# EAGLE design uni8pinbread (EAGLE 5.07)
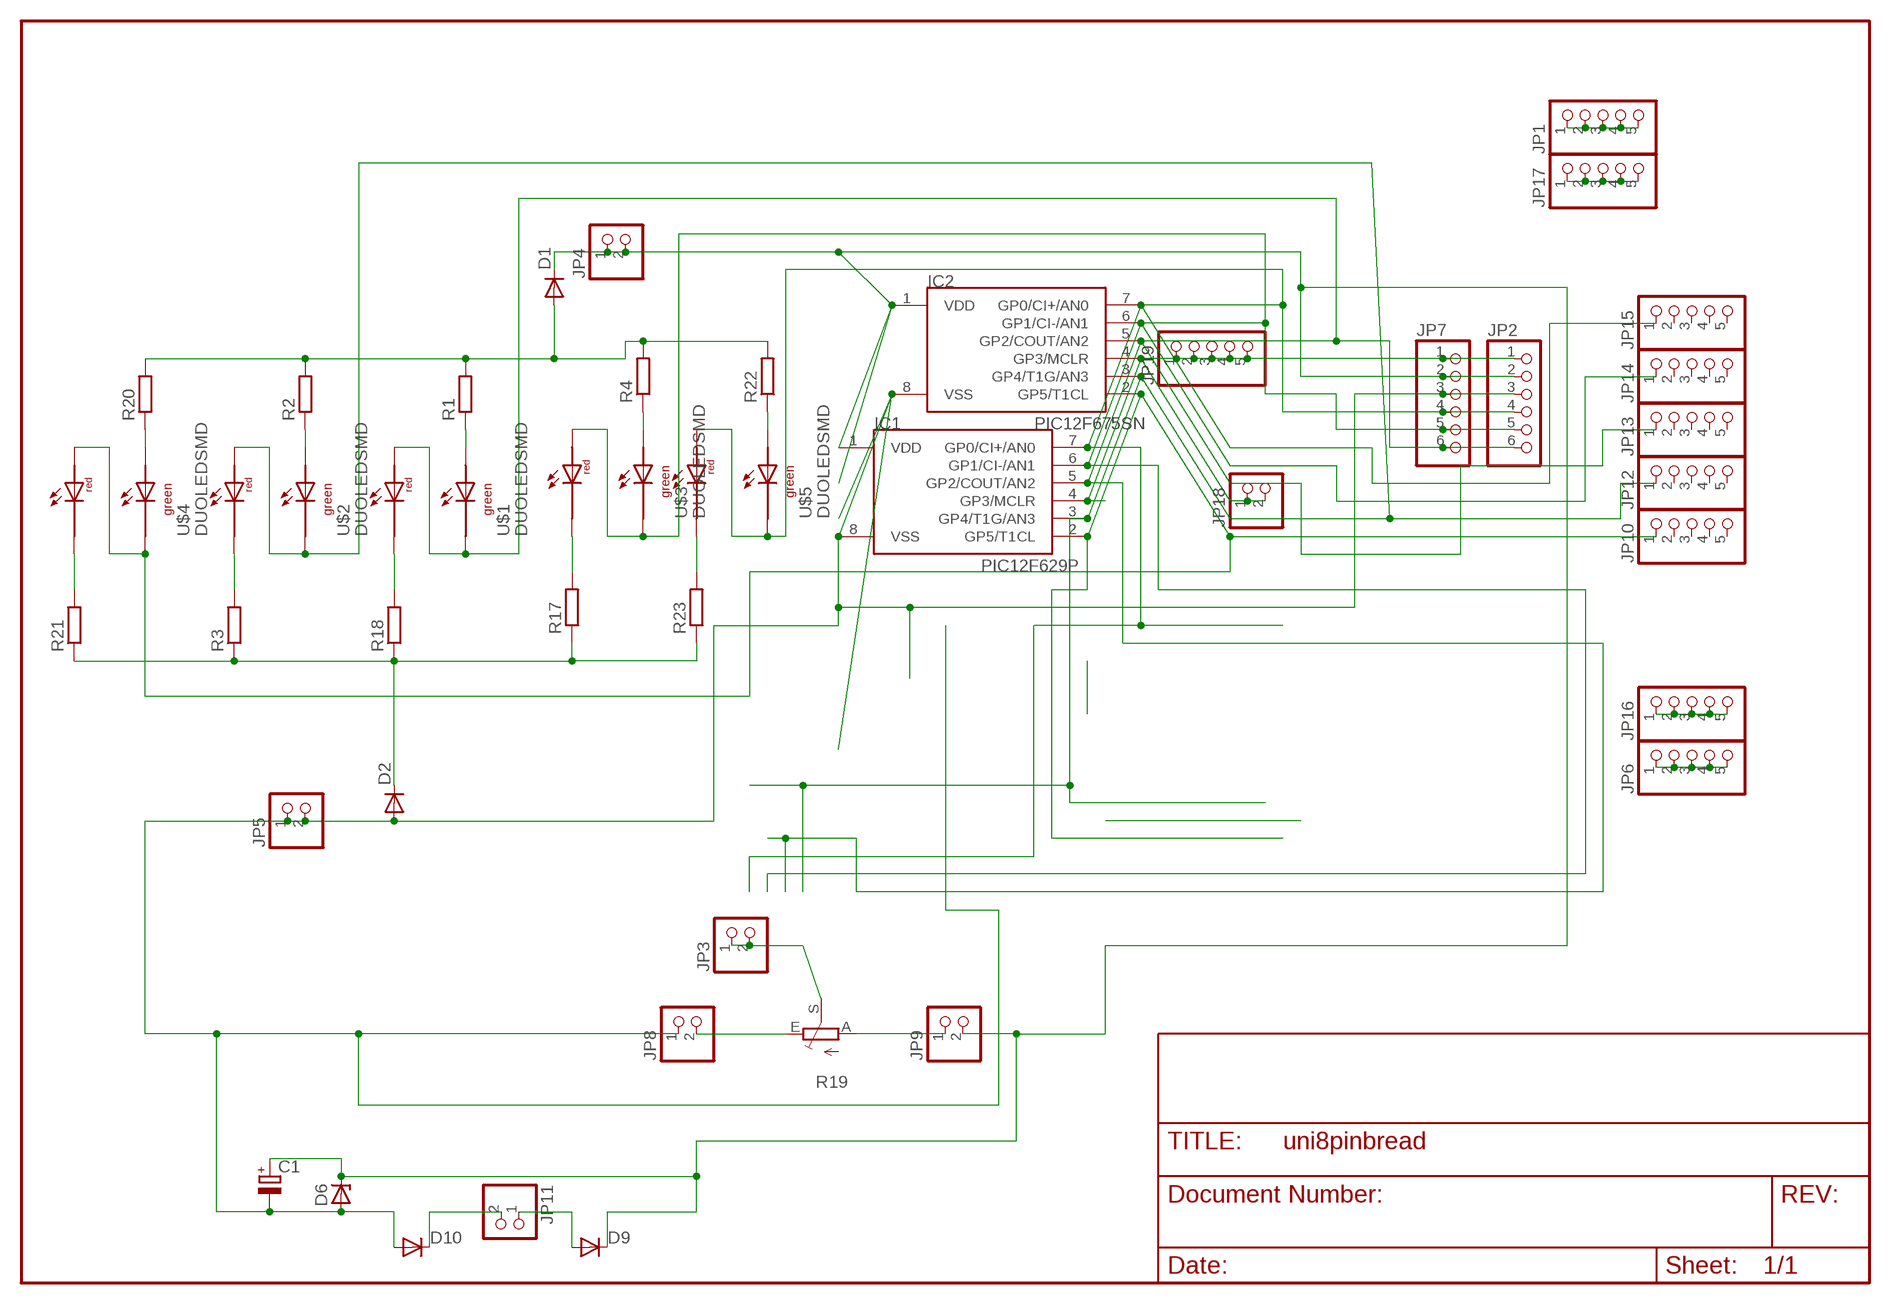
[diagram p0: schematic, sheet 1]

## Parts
C1  CPOL-EU5-13  [2,5-5-FLAT]
D1  DIODE-MINIMELF  [MINIMELF]
D2  DIODE-MINIMELF  [MINIMELF]
D6  ZENER-DIODEZD-2.5  [ZDIO-2.5]
D9  DIODE-D-5  [D-5]
D10  DIODE-D-5  [D-5]
IC1  PIC12F629P  [DIL8]
IC2  PIC12F675SN  [SO-08]
JP1  PINHD-1X5  [1X05]
JP2  PINHD-1X6  [1X06]
JP3  PINHD-1X2  [1X02]
JP4  PINHD-1X2  [1X02]
JP5  PINHD-1X2  [1X02]
JP6  PINHD-1X5  [1X05]
JP7  PINHD-1X6  [1X06]
JP8  PINHD-1X2  [1X02]
JP9  PINHD-1X2  [1X02]
JP10  PINHD-1X5  [1X05]
JP11  PINHD-1X2  [1X02]
JP12  PINHD-1X5  [1X05]
JP13  PINHD-1X5  [1X05]
JP14  PINHD-1X5  [1X05]
JP15  PINHD-1X5  [1X05]
JP16  PINHD-1X5  [1X05]
JP17  PINHD-1X5  [1X05]
JP18  PINHD-1X2  [1X02]
JP19  PINHD-1X5  [1X05]
R1  R-EU_R0805  [R0805]
R2  R-EU_R0805  [R0805]
R3  R-EU_R0805  [R0805]
R4  R-EU_R0805  [R0805]
R17  R-EU_R0805  [R0805]
R18  R-EU_R0805  [R0805]
R19  TRIM_EU-RAND160  [RANDL]
R20  R-EU_R0805  [R0805]
R21  R-EU_R0805  [R0805]
R22  R-EU_R0805  [R0805]
R23  R-EU_R0805  [R0805]
U$1  DUOLEDSMD  [DUOLEDSMD]
U$2  DUOLEDSMD  [DUOLEDSMD]
U$3  DUOLEDSMD  [DUOLEDSMD]
U$4  DUOLEDSMD  [DUOLEDSMD]
U$5  DUOLEDSMD  [DUOLEDSMD]

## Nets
GP0: IC1.7(GP0/CI+/AN0) IC2.7(GP0/CI+/AN0) JP2.4 JP7.4 JP15.1 U$5.ARED U$5.CGRN
GP1: IC1.6(GP1/CI-/AN1) IC2.6(GP1/CI-/AN1) JP2.5 JP7.5 JP14.1 U$3.ARED U$3.CGRN
GP2: IC1.5(GP2/COUT/AN2) IC2.5(GP2/COUT/AN2) JP2.6 JP7.6 JP13.1 U$1.ARED U$1.CGRN
GP4: IC1.3(GP4/T1G/AN3) IC2.3(GP4/T1G/AN3) JP12.1 U$2.ARED U$2.CGRN
GP5: IC1.2(GP5/T1CL) IC2.2(GP5/T1CL) JP10.1 U$4.ARED U$4.CGRN
N$1: D2.C R3.1 R17.1 R18.1 R21.1 R23.1
N$2: R2.1 U$2.AGRN
N$3: R1.1 U$1.AGRN
N$5: C1.- D2.A D6.A D10.A IC1.8(VSS) IC2.8(VSS) JP2.3 JP5.1 JP5.2 JP7.3 JP8.1
N$6: C1.+ D1.C D6.C D9.C IC1.1(VDD) IC2.1(VDD) JP2.2 JP4.1 JP4.2 JP7.2 JP9.2
N$7: R18.2 U$1.CRED
N$8: D1.A R1.2 R2.2 R4.2 R20.2 R22.2
N$11: IC1.4(GP3/MCLR) IC2.4(GP3/MCLR) JP2.1 JP7.1 JP18.1 JP18.2 JP19.1 JP19.2 JP19.3 JP19.4 JP19.5
N$12: JP1.1 JP1.2 JP1.3 JP1.4 JP1.5
N$13: JP17.1 JP17.2 JP17.3 JP17.4 JP17.5
N$14: JP16.1 JP16.2 JP16.3 JP16.4 JP16.5
N$15: JP6.1 JP6.2 JP6.3 JP6.4 JP6.5
N$27: R3.2 U$2.CRED
N$28: JP3.1 JP3.2 R19.S
N$29: R4.1 U$3.AGRN
N$31: JP9.1 R19.A
N$32: JP8.2 R19.E
N$33: R17.2 U$3.CRED
N$34: D10.C JP11.2
N$35: D9.A JP11.1
N$36: R20.1 U$4.AGRN
N$38: R21.2 U$4.CRED
N$39: R22.1 U$5.AGRN
N$41: R23.2 U$5.CRED
Unconnected: JP10.2 JP10.3 JP10.4 JP10.5 JP12.2 JP12.3 JP12.4 JP12.5 JP13.2 JP13.3 JP13.4 JP13.5 JP14.2 JP14.3 JP14.4 JP14.5 JP15.2 JP15.3 JP15.4 JP15.5

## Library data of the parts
C1 = rcl-2:CPOL-EU: POLARIZED CAPACITOR, European symbol
D1 D2 = diode:DIODE-: DIODE
D6 = diode-1:ZENER-DIODE: Z-Diode
D9 D10 = diode-1:DIODE-: DIODE
IC1 IC2 = microchip-5:PIC12F6*: uPC nW 1k Program Flash memory 2x Timer Comparator 10b A/D converter/ 4xIN
JP1 JP6 JP10 JP12-JP17 JP19 = pinhead(2):PINHD-1X5: PIN HEADER
JP2 JP7 = pinhead:PINHD-1X6: PIN HEADER
JP3-JP5 JP8 JP9 JP11 JP18 = pinhead(2):PINHD-1X2: PIN HEADER
R1-R4 R17 R18 R20-R23 = rcl:R-EU_: RESISTOR, European symbol
R19 = pot:TRIM_EU-: POTENTIOMETER
U$1-U$5 = led:DUOLEDSMD

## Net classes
0 default: width 0.3 mm, drill 0.6 mm, clearance 0.2 mm
1 power: width 0.4 mm, drill 0.6 mm, clearance 0.2 mm

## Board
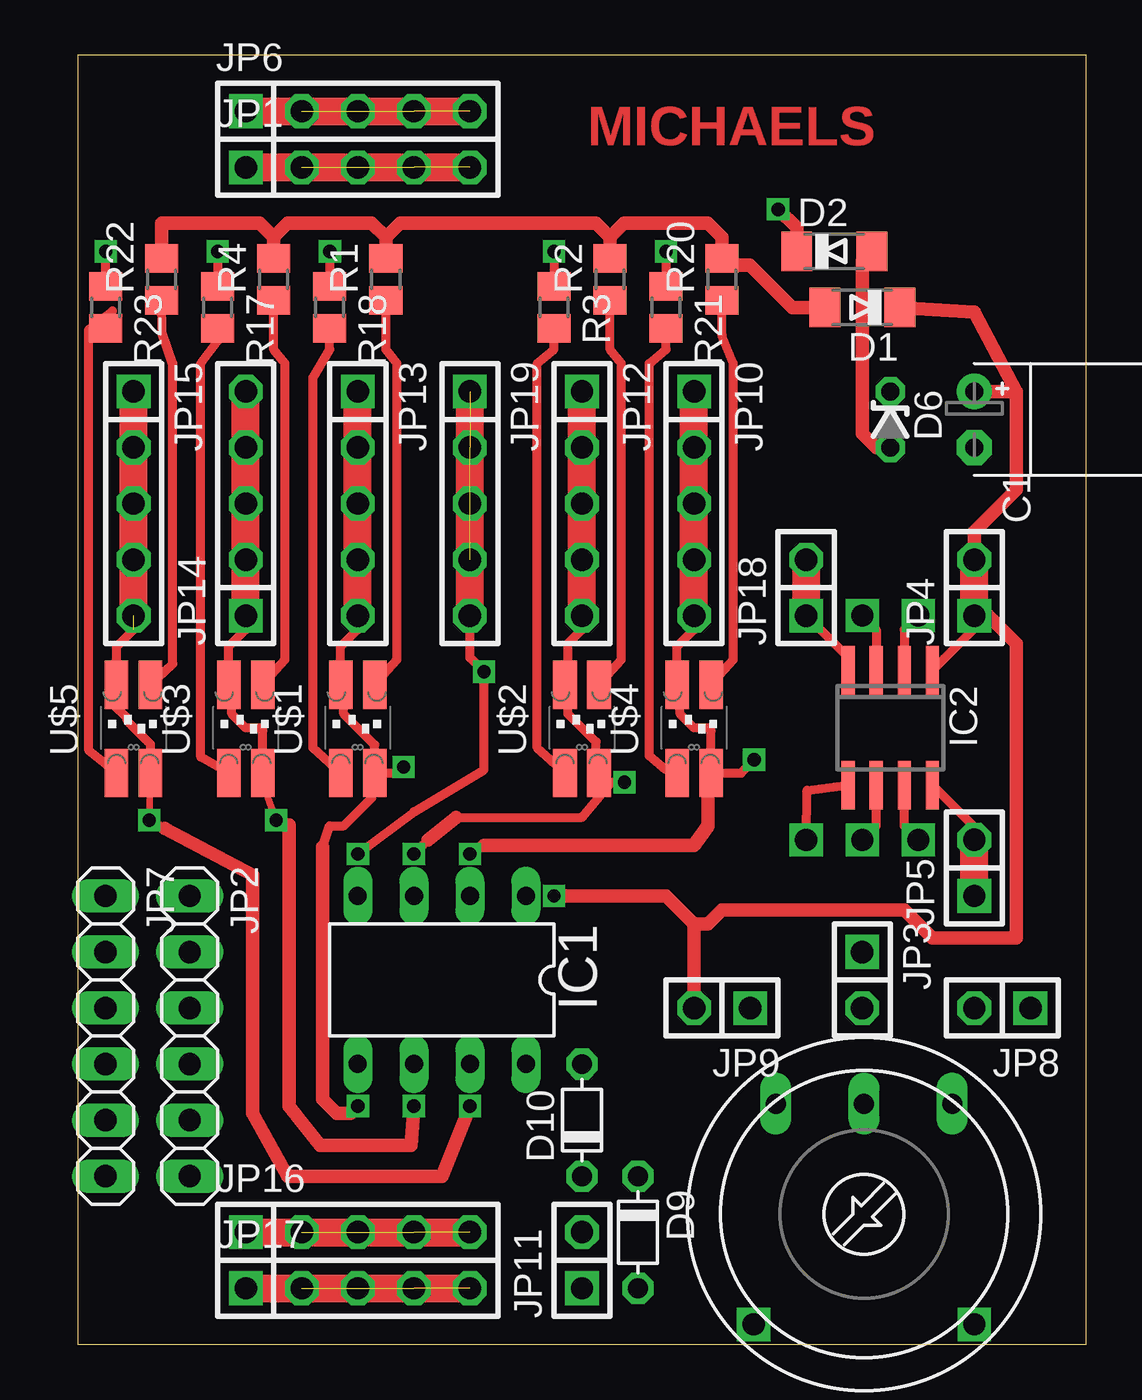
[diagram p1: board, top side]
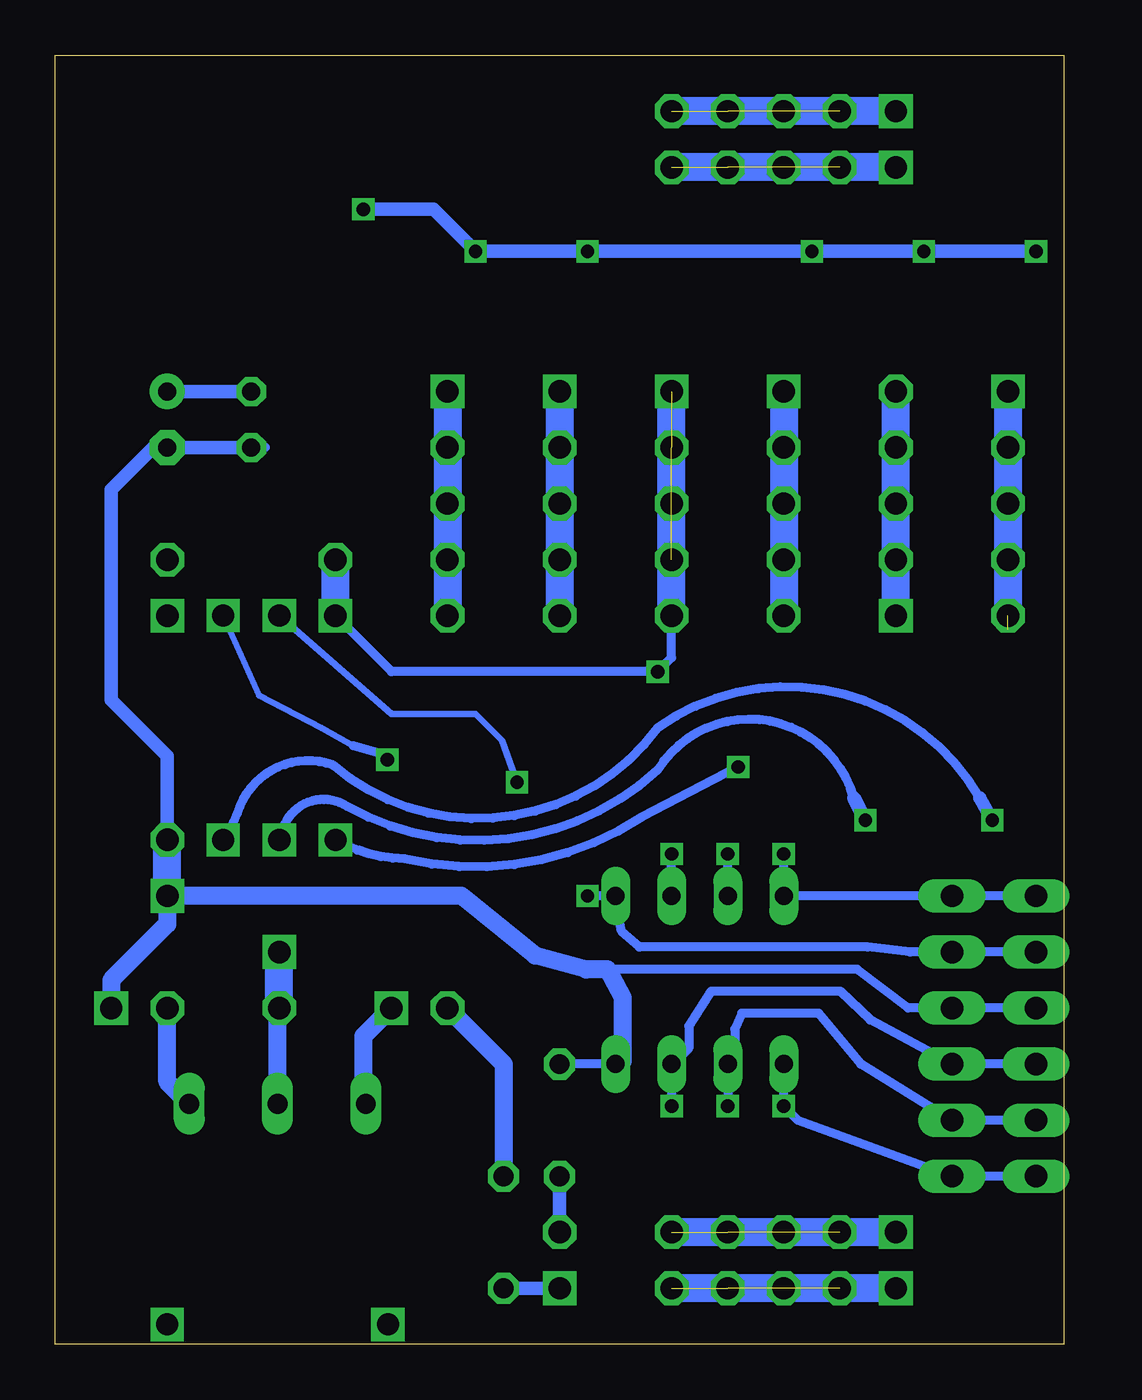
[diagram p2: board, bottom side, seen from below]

Size 45.72 x 58.42 mm. Coordinates in mm from the lower left corner, seen from the top.
Outline: 0,0 45.72,0 45.72,58.42 0,58.42 0,0
Copper layers (1*16): Top 0.035mm / dielectric 1.5mm / Bottom 0.035mm
Design rules "default": minimum track width 10mil, minimum drill 24mil, track to track 8mil, track to pad 8mil, pad to pad 8mil, via to via 8mil, smd to smd 8mil, copper to edge 40mil, drill to drill 8mil, minimum pad ring 10mil, minimum via ring 8mil, stop-mask expansion 4mil, vias tented up to drill 0mil, thermal gap 10mil

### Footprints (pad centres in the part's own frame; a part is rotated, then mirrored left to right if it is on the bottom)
2,5-5-FLAT = drill 0.813 pad 1.6 round: + -1.27,0 | drill 0.813 pad 1.6 octagon: - 1.27,0
MINIMELF = smd 1.4 x 1.8: A 1.7,0; C -1.7,0
ZDIO-2.5 = drill 0.813 octagon: A 1.27,0; C -1.27,0
D-5 = drill 0.9 octagon: A 2.54,0; C -2.54,0
DIL8 = drill 0.813 long: 1 -3.81,-3.81; 2 -1.27,-3.81; 3 1.27,-3.81; 4 3.81,-3.81; 5 3.81,3.81; 6 1.27,3.81; 7 -1.27,3.81; 8 -3.81,3.81
SO-08 = smd 0.6 x 2.2: 1 -1.905,-2.6; 2 -0.635,-2.6; 3 0.635,-2.6; 4 1.905,-2.6; 5 1.905,2.6; 6 0.635,2.6; 7 -0.635,2.6; 8 -1.905,2.6
1X05 = drill 1.016 square: 1 -5.08,0 | drill 1.016 octagon: 2 -2.54,0; 3 0,0; 4 2.54,0; 5 5.08,0
1X06 = drill 1.016 long: 1 -6.35,0; 2 -3.81,0; 3 -1.27,0; 4 1.27,0; 5 3.81,0; 6 6.35,0
1X02 = drill 1.016 square: 1 -1.27,0 | drill 1.016 octagon: 2 1.27,0
R0805 = smd 1.3 x 1.5: 1 -0.95,0; 2 0.95,0
RANDL = drill 0.9 long: A -4,5; E 4,5; S 0,5 | drill 1 square: P$1 -5,-5; P$2 5,-5
DUOLEDSMD = smd 1.067 x 2.184: AGRN 0.77,1.95; ARED -0.77,1.95; CGRN 0.77,-2.05; CRED -0.77,-2.05

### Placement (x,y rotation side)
C1  40.64,41.91 270 top
D1  35.56,46.99 180 top
D2  34.29,49.53 0 top
D6  36.83,41.91 270 top
D9  25.4,5.08 270 top
D10  22.86,10.16 90 top
IC1  16.51,16.51 180 top
IC2  36.83,27.94 180 top
JP1  12.7,53.34 0 top
JP2  5.08,13.97 270 top
JP3  35.56,16.51 270 top
JP4  40.64,34.29 90 top
JP5  40.64,21.59 90 top
JP6  12.7,55.88 0 top
JP7  1.27,13.97 270 top
JP8  41.91,15.24 180 top
JP9  29.21,15.24 180 top
JP10  27.94,38.1 270 top
JP11  22.86,3.81 90 top
JP12  22.86,38.1 270 top
JP13  12.7,38.1 270 top
JP14  7.62,38.1 90 top
JP15  2.54,38.1 270 top
JP16  12.7,5.08 0 top
JP17  12.7,2.54 0 top
JP18  33.02,34.29 90 top
JP19  17.78,38.1 270 top
R1  13.97,48.26 90 top
R2  24.13,48.26 90 top
R3  21.59,46.99 270 top
R4  8.89,48.26 90 top
R17  6.35,46.99 270 top
R18  11.43,46.99 270 top
R19  35.64,5.9 0 top
R20  29.21,48.26 90 top
R21  26.67,46.99 270 top
R22  3.81,48.26 90 top
R23  1.27,46.99 270 top
U$1  12.7,27.94 0 top
U$2  22.86,27.94 0 top
U$3  7.62,27.94 0 top
U$4  27.94,27.94 0 top
U$5  2.54,27.94 0 top

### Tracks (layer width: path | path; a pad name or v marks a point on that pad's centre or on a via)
GP0  (via drill 0.6, 1)  (1 unrouted)
  Top 0.305: v3.25,23.75 U$5.CGRN
  Top 0.406: 3.38,25.82 U$5.CGRN 3.31,27.19 2.25,28.25 2.25,28.38 1.62,29 1.62,29.75 U$5.ARED 1.77,31.61 2.54,32.38 | 3.94,23.38 v3.25,23.75 | IC2.7 37.47,23.5 v38.1,22.86
  Top 0.61: v17.78,10.79 16.51,7.62 9.53,7.62 7.94,10.48 7.94,21.28 3.94,23.38
  Top 1.27: 2.54,33.02 JP15.1
  Bottom 0.406: JP7.4 JP2.4 8.78,14.7 10.13,16 16,16 17,14.42 17,13.42 17.51,12.91 IC1.7 v17.78,10.79 | 3.81,24.77 arc-95 18.41,27.94 arc94 33.12,26.25 arc-93 37.47,24.07 arc10 v38.1,22.86
  Bottom 0.61: v3.25,23.75 3.81,24.77
  Bottom 1.27: JP15.1 2.54,33.02
GP1  (via drill 0.6, 1)
  Top 0.305: v9,23.75 8.5,25.12 U$3.CGRN
  Top 0.406: 9.59,23.53 v9,23.75 | U$3.CGRN 8.39,27.8 8.26,27.94 7.62,27.94 6.99,28.57 6.99,29.75 U$3.ARED 6.85,31.61 7.62,32.38 JP14.1 | IC2.6 36.2,23.5 v35.56,22.86
  Top 0.61: v15.24,10.79 15.12,9.03 10.99,9.03 9.59,10.79 9.59,23.53
  Top 1.27: JP14.1 v7.62,43.18
  Bottom 0.406: JP7.5 JP2.5 9.21,12.7 11.11,15 14.61,15 14.92,14.29 14.92,13.02 IC1.6 v15.24,10.79 | 9.53,24.77 arc-132 18.41,26.04 arc72 32.5,24.38 arc-108 35.44,23.25
  Bottom 0.61: v9,23.75 9.53,24.77 | 35.44,23.25 v35.56,22.86
  Bottom 1.27: JP14.1 v7.62,43.18
GP2  (via drill 0.6, 1)
  Top 0.406: IC2.5 33.05,25.11 v33.02,22.86 | 11.11,22.54 11.43,23.5 12.06,23.5 13.34,24.77 13.34,25.75 U$1.CGRN | v12.7,10.79 12.38,10.48 | U$1.CGRN 14.49,25.89 v14.77,26.16 | U$1.CGRN 13.47,27.17 12.06,28.57 12.06,29.75 U$1.ARED 11.93,31.61 12.7,32.38 12.7,33.02
  Top 0.61: 11.11,22.54 11.11,11.11 11.75,10.48 12.38,10.48
  Top 1.27: 12.7,33.02 JP13.1
  Bottom 0.406: JP7.6 JP2.6 12.06,10.16 v12.7,10.79 IC1.5 | v14.77,26.16 19.12,23.9 arc47 29.88,22 arc29 v33.02,22.86
  Bottom 1.27: JP13.1 12.7,33.02
GP4  (via drill 0.6, 1)
  Top 0.406: v15.24,22.23 15.88,22.86 | 17.14,23.88 22.86,23.88 24.13,25.4 | 24.13,25.4 24.12,25.4 U$2.CGRN 23.5,26.02 23.5,27.3 22.23,28.57 22.23,30.02 | 22.23,30.02 U$2.ARED | IC2.3 36.2,32.38 v35.56,33.02 | v24.79,25.47 24.2,25.47 24.13,25.4 | 22.23,30.02 22.23,31.75 22.86,32.38 22.86,33.02
  Top 0.61: 15.88,22.86 17.14,23.88
  Top 1.27: 22.86,33.02 JP12.1
  Bottom 0.305: v35.56,33.02 30.48,28.57 26.67,28.57 25.47,27.38 v24.79,25.47
  Bottom 0.406: IC1.3 v15.24,22.23
  Bottom 1.27: JP12.1 22.86,33.02
GP5  (via drill 0.6, 1)
  Top 0.406: v17.78,22.23 18.41,22.61 | IC2.2 37.47,32.38 v38.1,33.02 | 28.57,25.75 U$4.CGRN | U$4.CGRN 30.07,25.89 v30.66,26.49 | U$4.CGRN 28.71,27.8 28.57,27.94 27.94,27.94 27.3,28.57 27.3,29.75 U$4.ARED 27.17,31.61 27.94,32.38 27.94,33.02
  Top 0.61: 18.41,22.61 27.94,22.61 28.57,23.5 28.57,25.75
  Top 1.27: 27.94,33.02 JP10.1
  Bottom 0.305: v38.1,33.02 36.48,29.39 33.66,27.94 32.2,27.12
  Bottom 0.406: IC1.2 v17.78,22.23 | 32.2,27.12 30.93,26.76 v30.66,26.49
  Bottom 1.27: JP10.1 27.94,33.02
N$1  (via drill 0.6)
  Top 0.406: v26.67,49.53 R21.1 | v21.59,49.53 R3.1 | v11.43,49.53 R18.1 | v6.35,49.53 R17.1 | R23.1 v1.27,49.53
  Top 0.61: D2.C 32.59,50.59 v31.75,51.44
  Bottom 0.61: v31.75,51.44 28.57,51.44 v26.67,49.53 v21.59,49.53 v11.43,49.53 v6.35,49.53 v1.27,49.53
N$2
  Top 0.406: R2.1 24.13,45.09 24.64,44.45 24.64,31.02 U$2.AGRN
N$3
  Top 0.406: R1.1 13.97,45.09 14.48,44.45 14.48,31.02 U$1.AGRN
N$5
  Top 0.406: D6.A 36.2,40.64 | 35.56,49.1 D2.A | JP5.2 40.64,23.43 IC2.8
  Top 0.61: 36.2,40.64 35.56,41.27 35.56,49.1
  Top 1.27: JP5.1 JP5.2
  Bottom 0.406: JP7.3 JP2.3 7.07,15.24 9.38,17 20.7,17 | 20,12.84 IC1.8 D10.A | D6.A 36.2,40.64 | 41.27,40.64 C1.- | 40.64,23.5 40.61,23.46 40.61,22.89 JP5.2
  Bottom 0.61: C1.- D6.A | 41.27,40.64 43.18,38.73 43.18,29.21 40.64,26.67 40.64,23.5
  Bottom 0.813: 20,12.84 20,15.72 20.7,17 21.65,16.98 23.97,17.62 27.3,20.32 JP5.1 40.64,19.05 43.18,16.51 JP8.1
  Bottom 1.27: JP5.1 JP5.2
N$6  (via drill 0.6)
  Top 0.406: IC2.1 40.64,32.45 JP4.1 41.27,33.02
  Top 0.61: 27.94,19.05 JP9.2 | 27.94,19.05 26.67,20.32 v21.59,20.32 | 27.94,19.05 28.57,19.05 29.21,19.68 37.47,19.68 38.73,18.41 42.55,18.41 42.55,31.75 41.27,33.02 | JP4.2 40.64,36.83 42.55,38.73 42.55,43.18 | 42.55,43.18 40.64,46.78 D1.C | 42.55,43.18 C1.+
  Top 1.27: JP4.1 JP4.2
  Bottom 0.406: JP7.2 JP2.2 6.99,17.78 8.89,18 19.25,18 20.05,18.72 IC1.1 v21.59,20.32
  Bottom 0.61: C1.+ D6.C
  Bottom 0.813: D9.C 25.4,12.7 JP9.2
N$7
  Top 0.406: R18.2 11.43,45.09 10.67,43.81 10.67,27.02 U$1.CRED
N$8
  Top 0.406: R20.2 29.52,48.9
  Top 0.61: R22.2 3.81,50.8 8.26,50.8 8.89,50.16 | 8.89,50.16 R4.2 | 8.89,50.16 9.53,50.8 13.34,50.8 13.97,50.16 | 13.97,50.16 R1.2 | 13.97,50.16 14.61,50.8 23.5,50.8 24.13,50.16 | 24.13,50.16 R2.2 | D1.A 32.38,46.99 30.48,48.9 29.52,48.9 | R20.2 29.21,50.16 28.57,50.8 24.77,50.8 24.13,50.16
N$11  (via drill 0.6)  (3 unrouted)
  Top 0.406: v12.7,22.23 15.24,24.13 18.41,26.04 v18.41,30.48 17.78,31.11 JP19.5 | IC2.4 34.92,31.11 JP18.1
  Top 1.27: JP19.5 JP19.1 | JP18.1 JP18.2
  Bottom 0.406: JP7.1 JP2.1 IC1.4 v12.7,22.23 | JP19.5 17.78,31.11 v18.41,30.48 30.48,30.48 JP18.1
  Bottom 1.27: JP19.5 JP19.1 | JP18.1 JP18.2
N$12  (3 unrouted)
  Top 1.27: JP1.1 JP1.5
  Bottom 1.27: JP1.1 JP1.5
N$13  (3 unrouted)
  Top 1.27: JP17.1 JP17.5
  Bottom 1.27: JP17.1 JP17.5
N$14  (3 unrouted)
  Top 1.27: JP16.1 JP16.5
  Bottom 1.27: JP16.1 JP16.5
N$15  (3 unrouted)
  Top 1.27: JP6.1 JP6.5
  Bottom 1.27: JP6.1 JP6.5
N$27
  Top 0.406: R3.2 21.59,45.09 20.83,44.45 20.83,27.02 U$2.CRED
N$28
  Bottom 0.406: 35.64,15.16 JP3.2
  Bottom 0.813: R19.S 35.64,15.16
  Bottom 1.27: JP3.2 JP3.1
N$29
  Top 0.406: R4.1 8.89,45.09 9.4,44.45 9.4,31.02 U$3.AGRN
N$31
  Bottom 0.406: R19.A 31.75,11.01
  Bottom 0.813: JP9.1 31.75,13.97 31.75,11.01
N$32
  Bottom 0.813: JP8.2 40.64,11.9 R19.E
N$33
  Top 0.406: R17.2 6.37,45.48 5.59,44.45 5.59,26.61 U$3.CRED
N$34
  Bottom 0.61: JP11.2 D10.C
N$35
  Bottom 0.61: JP11.1 D9.A
N$36
  Top 0.406: R20.1 29.21,45.72 29.72,44.45 29.72,31.02 U$4.AGRN
N$38
  Top 0.406: R21.2 26.67,45.09 25.91,44.45 25.91,26.67 26.67,26.04 27.02,26.04 U$4.CRED
N$39
  Top 0.406: R22.1 3.83,45.83 4.32,44.45 4.32,30.83 U$5.AGRN
N$41
  Top 0.406: R23.2 1.59,46.84 0.51,46 0.51,26.91 U$5.CRED

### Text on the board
Top: MICHAELS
